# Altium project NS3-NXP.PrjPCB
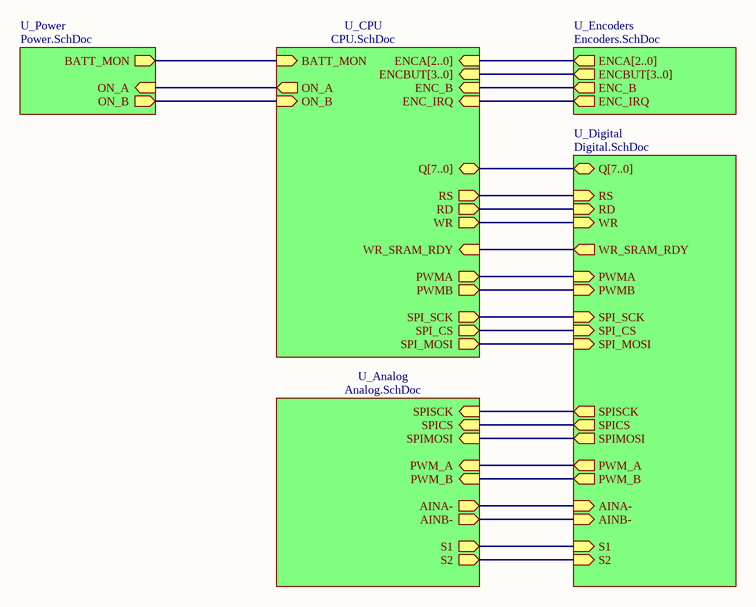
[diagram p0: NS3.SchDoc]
6 sheets, 304 parts. Net scope: hierarchical (ports join the sheet entries above them; power ports are global).
Board file: NS3-NXP.PcbDoc
Sheets:
  NS3.SchDoc
    U_Analog = Analog.SchDoc
    U_CPU = CPU.SchDoc
    U_Power = Power.SchDoc
    U_Digital = Digital.SchDoc
    U_Encoders = Encoders.SchDoc

## Sheet NS3.SchDoc: NeilScope-3 NXP
size A4; Engineer: Serj_K; Revision: 1.1; SheetNumber: 1; SheetTotal: 6; PageSetup: Record=PageOptions|CenterHorizontal=True|CenterVertical=True|PrintScale=1.00|XCorrection=1.00|YCorrection=1.00|PrintKind=0|BorderSize=5000000|LeftOffset=0|BottomOffset=0|Orientation=2|PaperLength=1000|PaperWidth=1000|Scale=100|PaperSource=7|PrintQuality=-4|MediaType=1|DitherType=10|PaperKind=A4|PrintScaleMode=1

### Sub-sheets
U_Analog = Analog.SchDoc: PWM_A (in), PWM_B (in), AINA- (out), AINB- (out), SPISCK (in), SPICS (in), SPIMOSI (in), S1 (out), S2 (out)
U_CPU = CPU.SchDoc: Q[7..0] (bidir), BATT_MON (in), RS (out), RD (out), ON_B (in), ON_A (out), WR (out), WR_SRAM_RDY (in), ENCA[2..0] (in), ENCBUT[3..0] (in), ENC_B (in), ENC_IRQ (in), PWMA (out), PWMB (out), SPI_SCK (out), SPI_CS (out), SPI_MOSI (out)
U_Digital = Digital.SchDoc: AINA- (in), AINB- (in), WR_SRAM_RDY (out), RS (in), RD (in), WR (in), Q[7..0] (bidir), PWM_A (out), PWM_B (out), PWMA (in), PWMB (in), SPISCK (out), SPICS (out), SPIMOSI (out), SPI_SCK (in), SPI_CS (in), SPI_MOSI (in), S1 (in), S2 (in)
U_Encoders = Encoders.SchDoc: ENC_B (out), ENC_IRQ (out), ENCA[2..0] (out), ENCBUT[3..0] (out)
U_Power = Power.SchDoc: BATT_MON (out), ON_B (out), ON_A (in)

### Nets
ENC_B: sheet U_CPU/ENC_B, sheet U_Encoders/ENC_B
ENC_IRQ: sheet U_CPU/ENC_IRQ, sheet U_Encoders/ENC_IRQ
ON_A: sheet U_CPU/ON_A, sheet U_Power/ON_A
ON_B: sheet U_CPU/ON_B, sheet U_Power/ON_B
PWMA: sheet U_CPU/PWMA, sheet U_Digital/PWMA
PWMB: sheet U_CPU/PWMB, sheet U_Digital/PWMB
RD: sheet U_CPU/RD, sheet U_Digital/RD
RS: sheet U_CPU/RS, sheet U_Digital/RS
S1: sheet U_Analog/S1, sheet U_Digital/S1
S2: sheet U_Analog/S2, sheet U_Digital/S2
SPI_CS: sheet U_CPU/SPI_CS, sheet U_Digital/SPI_CS
SPI_MOSI: sheet U_CPU/SPI_MOSI, sheet U_Digital/SPI_MOSI
SPI_SCK: sheet U_CPU/SPI_SCK, sheet U_Digital/SPI_SCK
SPICS: sheet U_Analog/SPICS, sheet U_Digital/SPICS
SPIMOSI: sheet U_Analog/SPIMOSI, sheet U_Digital/SPIMOSI
SPISCK: sheet U_Analog/SPISCK, sheet U_Digital/SPISCK
WR: sheet U_CPU/WR, sheet U_Digital/WR
WR_SRAM_RDY: sheet U_CPU/WR_SRAM_RDY, sheet U_Digital/WR_SRAM_RDY
NetC84_2: sheet U_CPU/BATT_MON, sheet U_Power/BATT_MON
NetR105_2: sheet U_Analog/PWM_A, sheet U_Digital/PWM_A
NetR125_2: sheet U_Analog/PWM_B, sheet U_Digital/PWM_B
NetU4_3: sheet U_Analog/AINA-, sheet U_Digital/AINA-
NetU4_10: sheet U_Analog/AINB-, sheet U_Digital/AINB-

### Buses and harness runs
bus sheet U_CPU/ENCA[2..0] = sheet U_Encoders/ENCA[2..0]
bus sheet U_CPU/ENCBUT[3..0] = sheet U_Encoders/ENCBUT[3..0]
bus sheet U_CPU/Q[7..0] = sheet U_Digital/Q[7..0]

## Sheet Analog.SchDoc: NeilScope-3 NXP   Analog
size A4; Engineer: Serj_K; Revision: 1.1; SheetNumber: 2; SheetTotal: 6
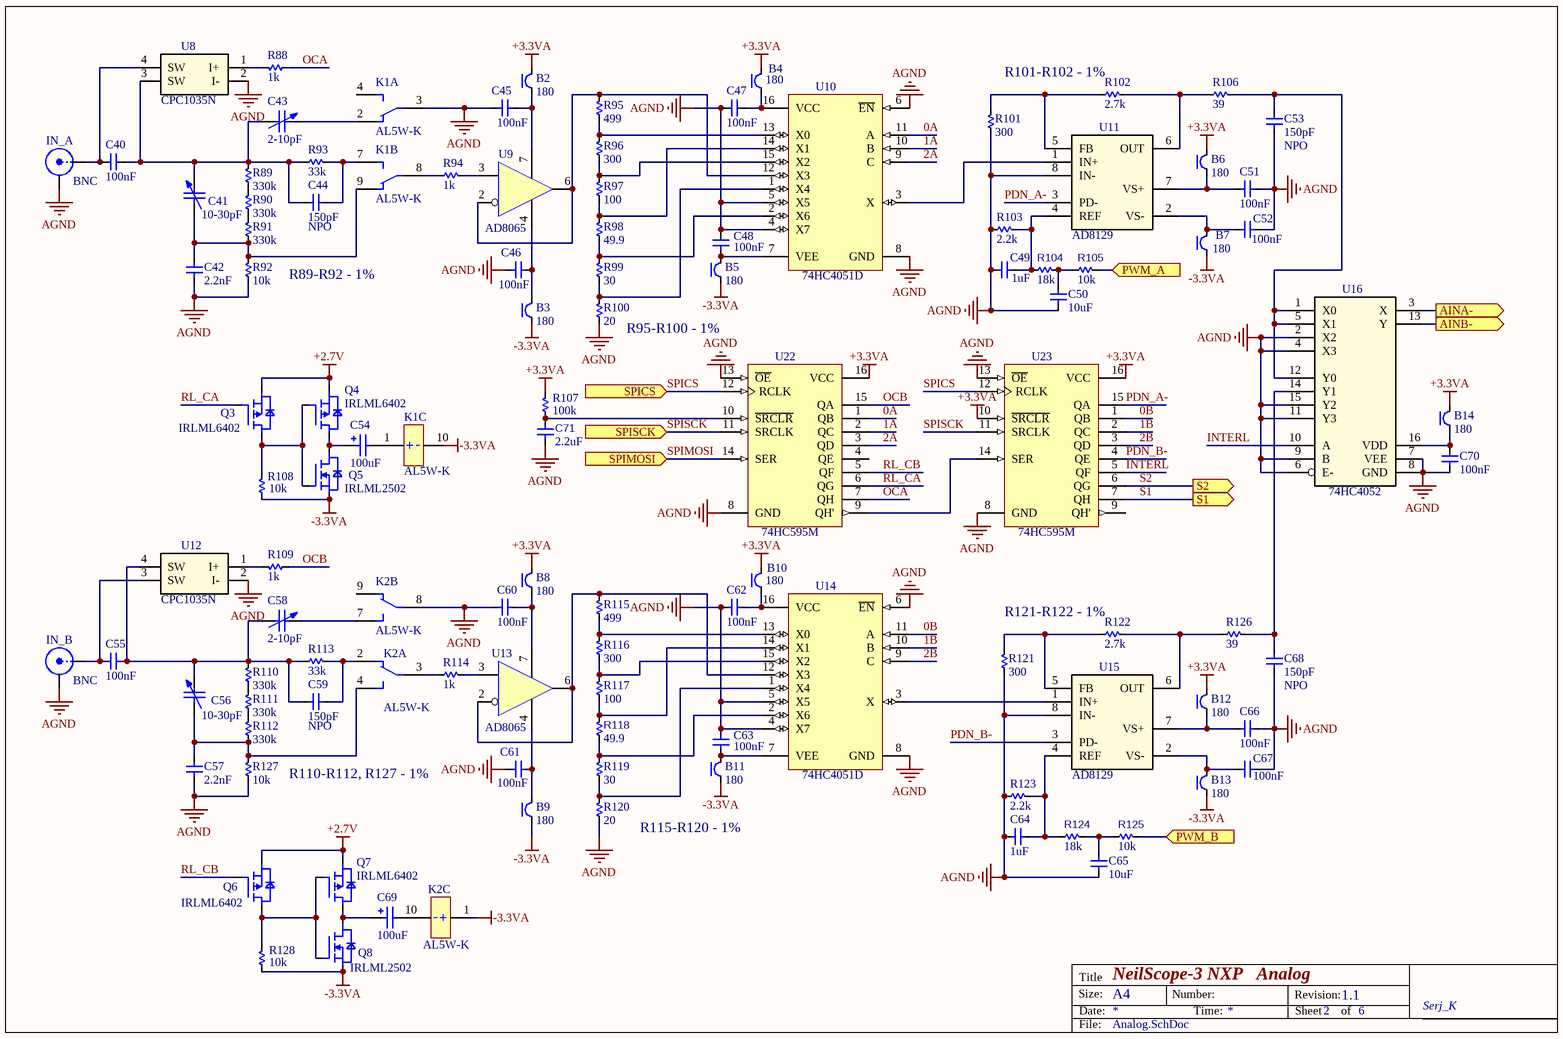
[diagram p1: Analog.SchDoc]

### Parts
B2  value 180  [C0603NH080]  (hidden comment: BEAD)
B3  value 180  [C0603NH080]  (hidden comment: BEAD)
B4  value 180  [C0603NH080]  (hidden comment: BEAD)
B5  value 180  [C0603NH080]  (hidden comment: BEAD)
B6  value 180  [C0603NH080]  (hidden comment: BEAD)
B7  value 180  [C0603NH080]  (hidden comment: BEAD)
B8  value 180  [C0603NH080]  (hidden comment: BEAD)
B9  value 180  [C0603NH080]  (hidden comment: BEAD)
B10  value 180  [C0603NH080]  (hidden comment: BEAD)
B11  value 180  [C0603NH080]  (hidden comment: BEAD)
B12  value 180  [C0603NH080]  (hidden comment: BEAD)
B13  value 180  [C0603NH080]  (hidden comment: BEAD)
B14  value 180  [C0603NH080]  (hidden comment: BEAD)
C40  value 100nF  [C1206NH190]  (hidden comment: Cap)
C41  value 10-30pF  [Cap_Var]  (hidden comment: Cap_Var)
C42  value 2.2nF  [C0805NH145]  (hidden comment: Cap)
C43  value 2-10pF  [Cap_Var]  (hidden comment: Cap_Var)
C44  NPO  value 150pF  [C0603NH080]
C45  value 100nF  [C0603NH080]  (hidden comment: Cap)
C46  value 100nF  [C0603NH080]  (hidden comment: Cap)
C47  value 100nF  [C0603NH080]  (hidden comment: Cap)
C48  value 100nF  [C0603NH080]  (hidden comment: Cap)
C49  value 1uF  [C0603NH080]  (hidden comment: Cap)
C50  value 10uF  [C0805NH145]  (hidden comment: Cap)
C51  value 100nF  [C0603NH080]  (hidden comment: Cap)
C52  value 100nF  [C0603NH080]  (hidden comment: Cap)
C53  NPO  value 150pF  [C0603NH080]
C54  CE_Al  [CE_D8_3.5]  (value not drawn)
C55  value 100nF  [C1206NH190]  (hidden comment: Cap)
C56  value 10-30pF  [Cap_Var]  (hidden comment: Cap_Var)
C57  value 2.2nF  [C0805NH145]  (hidden comment: Cap)
C58  value 2-10pF  [Cap_Var]  (hidden comment: Cap_Var)
C59  NPO  value 150pF  [C0603NH080]
C60  value 100nF  [C0603NH080]  (hidden comment: Cap)
C61  value 100nF  [C0603NH080]  (hidden comment: Cap)
C62  value 100nF  [C0603NH080]  (hidden comment: Cap)
C63  value 100nF  [C0603NH080]  (hidden comment: Cap)
C64  value 1uF  [C0603NH080]  (hidden comment: Cap)
C65  value 10uF  [C0805NH145]  (hidden comment: Cap)
C66  value 100nF  [C0603NH080]  (hidden comment: Cap)
C67  value 100nF  [C0603NH080]  (hidden comment: Cap)
C68  NPO  value 150pF  [C0603NH080]
C69  CE_Al  [CE_D8_3.5]  (value not drawn)
C70  value 100nF  [C0603NH080]  (hidden comment: Cap)
C71  value 2.2uF  [C0603_Murata]  (hidden comment: Cap)
IN_A  BNC  [BNC_RA CON]
IN_B  BNC  [BNC_RA CON]
K1  Part Label: AL5W-K  [DIP10_Relay]  (hidden comment: AxW-K-x)  (parts A,B,C of 3)
K2  Part Label: AL5W-K  [DIP10_Relay]  (hidden comment: AxW-K-x)  (parts A,B,C of 3)
Q3  Part Label: IRLML6402  [SOT23-3_DISCRETE]  (hidden comment: IRLML6302)
Q4  Part Label: IRLML6402  [SOT23-3_DISCRETE]  (hidden comment: IRLML6302)
Q5  Part Label: IRLML2502  [SOT23-3_DISCRETE]  (hidden comment: IRLML2402)
Q6  Part Label: IRLML6402  [SOT23-3_DISCRETE]  (hidden comment: IRLML6302)
Q7  Part Label: IRLML6402  [SOT23-3_DISCRETE]  (hidden comment: IRLML6302)
Q8  Part Label: IRLML2502  [SOT23-3_DISCRETE]  (hidden comment: IRLML2402)
R88  value 1k  [R0603N]  (hidden comment: R)
R89  value 330k  [R0805NH070]  (hidden comment: R)
R90  value 330k  [R0805NH070]  (hidden comment: R)
R91  value 330k  [R0805NH070]  (hidden comment: R)
R92  value 10k  [R0805NH070]  (hidden comment: R)
R93  value 33k  [R0805NH070]  (hidden comment: R)
R94  value 1k  [R0805NH070]  (hidden comment: R)
R95  value 499  [R0603N]  (hidden comment: R)
R96  value 300  [R0603N]  (hidden comment: R)
R97  value 100  [R0603N]  (hidden comment: R)
R98  value 49.9  [R0603N]  (hidden comment: R)
R99  value 30  [R0603N]  (hidden comment: R)
R100  value 20  [R0603N]  (hidden comment: R)
R101  value 300  [R0603N]  (hidden comment: R)
R102  value 2.7k  [R0603N]  (hidden comment: R)
R103  value 2.2k  [R0603N]  (hidden comment: R)
R104  value 18k  [R0805_YAGEO]  (hidden comment: R)
R105  value 10k  [R0603_UniOhm]  (hidden comment: R)
R106  value 39  [R0603N]  (hidden comment: R)
R107  value 100k  [R0603N]  (hidden comment: R)
R108  value 10k  [R0603N]  (hidden comment: R)
R109  value 1k  [R0603N]  (hidden comment: R)
R110  value 330k  [R0805NH070]  (hidden comment: R)
R111  value 330k  [R0805NH070]  (hidden comment: R)
R112  value 330k  [R0805NH070]  (hidden comment: R)
R113  value 33k  [R0805NH070]  (hidden comment: R)
R114  value 1k  [R0805NH070]  (hidden comment: R)
R115  value 499  [R0603N]  (hidden comment: R)
R116  value 300  [R0603N]  (hidden comment: R)
R117  value 100  [R0603N]  (hidden comment: R)
R118  value 49.9  [R0805_UniOhm]  (hidden comment: R)
R119  value 30  [R0603N]  (hidden comment: R)
R120  value 20  [R0603N]  (hidden comment: R)
R121  value 300  [R0603N]  (hidden comment: R)
R122  value 2.7k  [R0603N]  (hidden comment: R)
R123  value 2.2k  [R0603N]  (hidden comment: R)
R124  value 18k  [R0805_YAGEO]  (hidden comment: R)
R125  value 10k  [R0603_UniOhm]  (hidden comment: R)
R126  value 39  [R0603N]  (hidden comment: R)
R127  value 10k  [R0805NH070]  (hidden comment: R)
R128  value 10k  [R0603N]  (hidden comment: R)
U8  CPC1035N  [SOIC-4N]
U9  AD8065  [SO8_N]
U10  74HC4051D  [751B-05_N]
U11  AD8129  [SO8_N]
U12  CPC1035N  [SOIC-4N]
U13  AD8065  [SO8_N]
U14  74HC4051D  [751B-05_N]
U15  AD8129  [SO8_N]
U16  74HC4052  [TSSOP16A]
U22  74HC595M  [SO16_N]
U23  74HC595M  [SO16_N]

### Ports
AINA- (out), AINB- (out), PWM_A (in), PWM_B (in), S1 (out), S2 (out), SPICS (in), SPIMOSI (in), SPISCK (in)

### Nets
+2.7V: Q3.2(S) Q4.2(S) Q6.2(S) Q7.2(S)
+3.3VA: B2.2 B4.2 B6.2 B8.2 B10.2 B12.2 B14.2 R107.2 U22.16(VCC) U23.10(~{SRCLR}) U23.16(VCC)
-3.3VA: B3.1 B5.1 B7.1 B9.1 B11.1 B13.1 K1.10(-) K2.1(+) Q5.2(S) Q8.2(S) R108.1 R128.1
AGND: C42.1 C45.1 C46.1 C47.2 C48.2 C49.1 C50.1 C51.2 C52.2 C53.1 C57.1 C60.1 C61.1 C62.2 C63.2 C64.1 C65.1 C66.2 C67.2 C68.1 C70.1 C71.1 IN_A.2(Y) IN_B.2(Y) K1.3(K1) K2.8(K2) R92.1 R100.1 R101.1 R103.1 R120.1 R121.1 R123.1 R127.1 U8.2(I-) U10.4(X7) U10.5(X5) U10.6(~{EN}) U10.8(GND) U11.8(IN-) U12.2(I-) U14.4(X7) U14.5(X5) U14.6(~{EN}) U14.8(GND) U15.8(IN-) U16.2(X2) U16.4(X3) U16.6(E-) U16.7(VEE) U16.8(GND) U16.9(B) U16.11(Y3) U16.15(Y2) U22.8(GND) U22.13(~{OE}) U23.8(GND) U23.13(~{OE})
0A: U10.11(A) U22.1(QB)
0B: U14.11(A) U23.1(QB)
1A: U10.10(B) U22.2(QC)
1B: U14.10(B) U23.2(QC)
2A: U10.9(C) U22.3(QD)
2B: U14.9(C) U23.3(QD)
INTERL: U16.10(A) U23.5(QF)
OCA: R88.1 U22.7(QH)
OCB: R109.1 U22.15(QA)
PDN_A-: U11.3(PD-) U23.15(QA)
PDN_B-: U15.3(PD-) U23.4(QE)
RL_CA: Q3.1(G) U22.6(QG)
RL_CB: Q6.1(G) U22.5(QF)
S1: U23.7(QH) ; port S1
S2: U23.6(QG) ; port S2
SPICS: U22.12(RCLK) U23.12(RCLK) ; port SPICS
SPIMOSI: U22.14(SER) ; port SPIMOSI
SPISCK: U22.11(SRCLK) U23.11(SRCLK) ; port SPISCK
NetB2_1: B2.1 C45.2 U9.7
NetB3_2: B3.2 C46.2 U9.4
NetB4_1: B4.1 C47.1 U10.16(VCC)
NetB5_2: B5.2 C48.1 U10.7(VEE)
NetB6_1: B6.1 C51.1 U11.7(VS+)
NetB7_2: B7.2 C52.1 U11.2(VS-)
NetB8_1: B8.1 C60.2 U13.7
NetB9_2: B9.2 C61.2 U13.4
NetB10_1: B10.1 C62.1 U14.16(VCC)
NetB11_2: B11.2 C63.1 U14.7(VEE)
NetB12_1: B12.1 C66.1 U15.7(VS+)
NetB13_2: B13.2 C67.1 U15.2(VS-)
NetB14_1: B14.1 C70.2 U16.16(VDD)
NetC40_1: C40.1 IN_A.1(X) U8.4(SW)
NetC40_2: C40.2 C41.2 C43.1 C44.1 R89.2 R93.1 U8.3(SW)
NetC41_1: C41.1 C42.2 K1.9(K21) R91.1 R92.2
NetC43_2: C43.2 K1.2(K11)
NetC44_2: C44.2 K1.7(K22) R93.2
NetC49_2: C49.2 R103.2 R104.1 U11.4(REF)
NetC50_2: C50.2 R104.2 R105.1
NetC53_2: C53.2 R106.2 U16.1(X0) U16.5(X1) U16.12(Y0)
NetC54_1: C54.1 Q4.3(D) Q5.3(D)
NetC54_2: C54.2 K1.1(+)
NetC55_1: C55.1 IN_B.1(X) U12.3(SW)
NetC55_2: C55.2 C56.2 C58.1 C59.1 R110.2 R113.1 U12.4(SW)
NetC56_1: C56.1 C57.2 K2.4(K12) R112.1 R127.2
NetC58_2: C58.2 K2.7(K22)
NetC59_2: C59.2 K2.2(K11) R113.2
NetC64_2: C64.2 R123.2 R124.1 U15.4(REF)
NetC65_2: C65.2 R124.2 R125.1
NetC68_2: C68.2 R126.2 U16.14(Y1)
NetC69_1: C69.1 Q7.3(D) Q8.3(D)
NetC69_2: C69.2 K2.10(-)
NetC71_2: C71.2 R107.1 U22.10(~{SRCLR})
NetK1_8: K1.8(K2) R94.1
NetK2_3: K2.3(K1) R114.1
NetQ3_3: Q3.3(D) Q4.1(G) Q5.1(G) R108.2
NetQ6_3: Q6.3(D) Q7.1(G) Q8.1(G) R128.2
NetR88_2: R88.2 U8.1(I+)
NetR89_1: R89.1 R90.2
NetR90_1: R90.1 R91.2
NetR94_2: R94.2 U9.3(In)
NetR95_1: R95.1 R96.2 U10.13(X0)
NetR95_2: R95.2 U9.2(In-) U9.6(Out) U10.12(X3)
NetR96_1: R96.1 R97.2 U10.15(X2)
NetR97_1: R97.1 R98.2 U10.14(X1)
NetR98_1: R98.1 R99.2 U10.2(X6)
NetR99_1: R99.1 R100.2 U10.1(X4)
NetR101_2: R101.2 R102.1 U11.5(FB)
NetR102_2: R102.2 R106.1 U11.6(OUT)
NetR105_2: R105.2 ; port PWM_A
NetR109_2: R109.2 U12.1(I+)
NetR110_1: R110.1 R111.2
NetR111_1: R111.1 R112.2
NetR114_2: R114.2 U13.3(In)
NetR115_1: R115.1 R116.2 U14.13(X0)
NetR115_2: R115.2 U13.2(In-) U13.6(Out) U14.12(X3)
NetR116_1: R116.1 R117.2 U14.15(X2)
NetR117_1: R117.1 R118.2 U14.14(X1)
NetR118_1: R118.1 R119.2 U14.2(X6)
NetR119_1: R119.1 R120.2 U14.1(X4)
NetR121_2: R121.2 R122.1 U15.5(FB)
NetR122_2: R122.2 R126.1 U15.6(OUT)
NetR125_2: R125.2 ; port PWM_B
NetU4_3: U16.3(X) ; port AINA-
NetU4_10: U16.13(Y) ; port AINB-
NetU10_3: U10.3(X) U11.1(IN+)
NetU14_3: U14.3(X) U15.1(IN+)
NetU22_9: U22.9(QH') U23.14(SER)

Not connected (* = marked no-connect by the designer): K1 4(K12); K2 9(K21); U22 4(QE); U23 9(QH')

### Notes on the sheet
- (near R102) R101-R102 - 1%
- R89-R92 - 1%
- R95-R100 - 1%
- (near R122) R121-R122 - 1%
- R110-R112, R127 - 1%
- R115-R120 - 1%

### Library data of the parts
B2-B14 = BLM18PG181SN1D: Bead 0603 size for power lines; Part Label: SMD Beads 180 1.5A; Manufacturer: muRata; Device: EMI; ShortName: SMD Beads
C40 C55 = GRM31C5C1H104JA01L: PartName: GRM31; Part Label: C1206 100nF 5% NP0 50V; Manufacturer: muRata; Voltage: 50V; Tolerance: 5 %; Device: C; ShortName: C1206
C41 C43 C56 C58 = Cap_Var: Variable or Adjustable Capacitor
C42 C57 = CL21C222JBFNNNE: PartName: CL21; Part Label: C0805 2.2nF 5% NP0 50V; Manufacturer: Samsung Electro-Mechanics; Voltage: 50V; Tolerance: 5 %; Device: C; ShortName: C0805
C44 C53 C59 C68 = C0603C151J5GAC7867: PartName: C0603C; Part Label: C0603 150pF 5% NP0 50V; Manufacturer: Kemet; Voltage: 50V; Tolerance: 5 %; Device: C; ShortName: C0603
C45-C48 C51 C52 C60-C63 C66 C67 C70 = CL10B104KB8NNNC: PartName: CL10; Part Label: C0603 100nF 10% X7R 50V; Manufacturer: Samsung Electro-Mechanics; Voltage: 50V; Tolerance: 10 %; Device: C; ShortName: C0603
C49 C64 = GRM188R61C225KE15D: PartName: GRM188; Part Label: C0603 2.2uF 10% X5R 16V; Manufacturer: muRata; Voltage: 16V; Tolerance: 10 %; Device: C; ShortName: C0603
C50 C65 = GRM21BR61A106KE19L: PartName: GRM21; Part Label: C0805 10uF 10% X5R 10V; Manufacturer: muRata; Voltage: 10V; Tolerance: 10 %; Device: C; ShortName: C0805
C54 C69 = CE_Al: Aluminium Electrolitic Capacitor
C71 = GRM188R61C225KE15D: General Purpose; PartName: GRM188; Part Label: C0603 2.2uF 10% X5R 16V; Manufacturer: muRata; Voltage: 16V; Tolerance: 10 %; Device: C; ShortName: C0603
IN_A IN_B = BNC: BNC Elbow Connector
K1 K2 = A–5W–K: 5V переключающее реле.; Part Number: A–5W–K; Manufacturer: Fujitsu; ClassName_u: Relay; Device: K
Q3 Q4 Q6 Q7 = IRLML6302TRPBF: 20V, 0.7A Single P-Channel HEXFET Power MOSFET; Manufacturer: International Rectifier; Device: Q; ShortName: PMOS
Q5 Q8 = IRLML2402TRPBF: 20V, 0.25 Ohm, Single N-Channel HEXFET Power MOSFET; Manufacturer: International Rectifier; Device: Q; ShortName: NMOS
R88 R109 = ERA3AED102V: PartName: ERA3A; Part Label: R0603 1k 0.5% TC25 75V; Manufacturer: Panasonic; TempCo: 25 ppm; Tolerance: 0.5 %; ClassName_u: SMD 0603 Thin Film; ShortName: R0603
R89-R91 R110-R112 R127 = 0805S8F5100T50: PartName: 0805S; Part Label: R0805 510 1% TC100 150V; Manufacturer: uniOhm; TempCo: 100 ppm; Tolerance: 1 %; ShortName: R0805
R92 R93 R113 = 0805S8F1002T50: PartName: 0805S; Part Label: R0805 10k 1% TC100 150V; Manufacturer: uniOhm; TempCo: 100 ppm; Tolerance: 1 %; ShortName: R0805
R94 R114 = 0805S8F1001T50: PartName: 0805S; Part Label: R0805 1k 1% TC100 150V; Manufacturer: uniOhm; TempCo: 100 ppm; Tolerance: 1 %; ShortName: R0805
R95 R115 = TC0350F4990T5E: TC03 (0603) 1/16W 1% 499E 50PPM T/R-5000; Part Label: R0603 499 1% TC50 50V; Manufacturer: uniOhm; ClassName_u: SMD 0603 Thin Film; ShortName: R0603
R96 R101 R116 R121 = 0603SAF3300T50: PartName: 0603SA; Part Label: R0603 330 1% TC100 50V; Manufacturer: uniOhm; TempCo: 100 ppm; Tolerance: 1 %; ShortName: R0603
R97 R117 = 0603SAF1000T50: PartName: 0603SA; Part Label: R0603 100 1% TC100 50V; Manufacturer: uniOhm; TempCo: 100 ppm; Tolerance: 1 %; ShortName: R0603
R98 = RR0816P-4992-D-68C: PartName: RR0816; Part Label: R0603 49.9k 0.5% TC25 50V; Manufacturer: SUSUMU; TempCo: 25 ppm; Tolerance: 0.5 %; ClassName_u: SMD 0603 Thin Film; ShortName: R0603
R99 R100 R119 R120 = 0603SAF330JT50: PartName: 0603SA; Part Label: R0603 33 1% TC100 50V; Manufacturer: uniOhm; TempCo: 100 ppm; Tolerance: 1 %; ShortName: R0603
R102 R103 R122 R123 = 0603SAF2701T50: PartName: 0603SA; Part Label: R0603 2.7k 1% TC100 50V; Manufacturer: uniOhm; TempCo: 100 ppm; Tolerance: 1 %; ShortName: R0603
R104 R124 = RC0805FR-0710KL: General Purpose Chip Resistor; Part Label: R0805 10k 1% TC100 300V; Manufacturer: YAGEO; TempCo: 100 ppm; Tolerance: 1 %; ShortName: R0805
R105 R125 = TC0350F1002T5E: TC03 (0603) 1/16W 1% 10.0K 50PPM T/R-5000; Part Label: R0603 10k 1% TC50 50V; Manufacturer: uniOhm; ClassName_u: SMD 0603 Thin Film; ShortName: R0603
R106 R126 = TC0310C3001T5E: TC03 (0603) 1/16W 0.25% 3.00K 10PPM T/R-5000; Part Label: R0603 3k 0.25% TC10 50V; Manufacturer: uniOhm; ClassName_u: SMD 0603 Thin Film; ShortName: R0603
R107 R108 R128 = 0603SAF1002T50: PartName: 0603SA; Part Label: R0603 10k 1% TC100 50V; Manufacturer: uniOhm; TempCo: 100 ppm; Tolerance: 1 %; ShortName: R0603
R118 = 0805S8F4700T50: PartName: 0805S; Part Label: R0805 470 1% TC100 150V; Manufacturer: uniOhm; TempCo: 100 ppm; Tolerance: 1 %; ShortName: R0805
U8 U12 = CPC1035N: Opto Switch
U10 U14 = MC74HC4051AD: Analog Multiplexer/Demultiplexer
U22 U23 = M74HC595M1R: 8 Bit Shift Register with Output Latches (3 STATE)

## Sheet CPU.SchDoc: NeilScope-3 NXP    CPU
size A4; Engineer: Serj_K; Revision: 1.1; SheetNumber: 3; SheetTotal: 6; PageSetup: Record=PageOptions|CenterHorizontal=True|CenterVertical=True|PrintScale=0.97|XCorrection=1.00|YCorrection=1.00|PrintKind=0|BorderSize=5000000|LeftOffset=0|BottomOffset=0|Orientation=2|PaperLength=1000|PaperWidth=1000|Scale=100|PaperSource=7|PrintQuality=-4|MediaType=1|DitherType=10|PaperKind=A4|PrintScaleMode=1
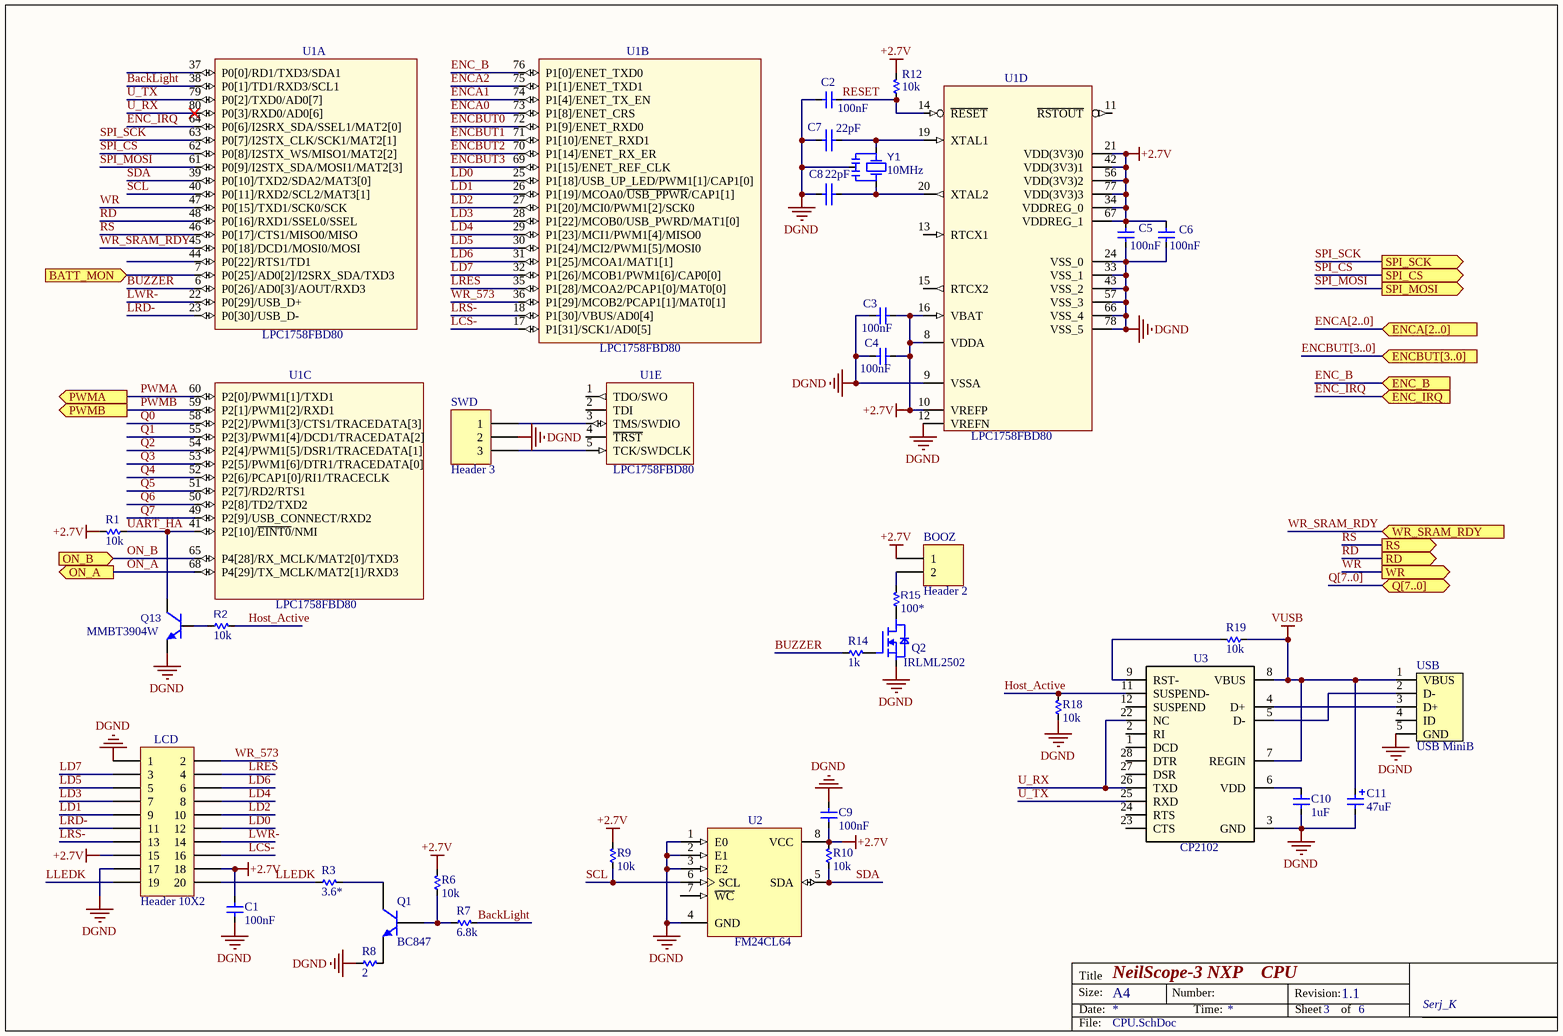
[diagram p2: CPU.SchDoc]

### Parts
BOOZ  Header 2  [HDR1X2]
C1  value 100nF  [C0603NH080]  (hidden comment: Cap)
C2  value 100nF  [C0603NH080]  (hidden comment: Cap)
C3  value 100nF  [C0603NH080]  (hidden comment: Cap)
C4  value 100nF  [C0603NH080]  (hidden comment: Cap)
C5  value 100nF  [C0603NH080]  (hidden comment: Cap)
C6  value 100nF  [C0603NH080]  (hidden comment: Cap)
C7  value 22pF  [C0603_Samsung]  (hidden comment: Cap)
C8  value 22pF  [C0603_Samsung]  (hidden comment: Cap)
C9  value 100nF  [C0603NH080]  (hidden comment: Cap)
C10  value 1uF  [C0603NH080]  (hidden comment: Cap)
C11  value 47uF  [CAPMP7343X280N]  (hidden comment: ECap)
LCD  Header 10X2  [HDR2X10]
Q1  BC847  [SOT23_N]
Q2  Part Label: IRLML2502  [SOT23-3_DISCRETE]  (hidden comment: IRLML2402)
Q13  Part Label: MMBT3904W  [SOT323]  (hidden comment: NPN)
R1  value 10k  [R0603_UniOhm]  (hidden comment: R)
R2  value 10k  [R0603_UniOhm]  (hidden comment: R)
R3  value 3.6*  [R1206NH084]  (hidden comment: R)
R6  value 10k  [R0603N]  (hidden comment: R)
R7  value 6.8k  [R0603N]  (hidden comment: R)
R8  value 2  [R1206NH084]  (hidden comment: R)
R9  value 10k  [R0603N]  (hidden comment: R)
R10  value 10k  [R0603N]  (hidden comment: R)
R12  value 10k  [R0603N]  (hidden comment: R)
R14  value 1k  [R0603N]  (hidden comment: R)
R15  value 100*  [R0603_UniOhm]  (hidden comment: R)
R18  value 10k  [R0603N]  (hidden comment: R)
R19  value 10k  [R0603N]  (hidden comment: R)
SWD  Header 3  [HDR1X3]
U1  LPC1758FBD80  [PQFP80]  (parts A,B,C,D,E of 5)
U2  FM24CL64  [SOP8_N]
U3  CP2102  [QFN-28]
USB  USB MiniB  [USB miniB (SMD NNM)]
Y1  value 10MHz  [CSTCE_G]  (hidden comment: XTAL_CAP)

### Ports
BATT_MON (in), ENC_B (in), ENC_IRQ (in), ENCA[2..0] (in), ENCBUT[3..0] (in), ON_A (out), ON_B (in), PWMA (out), PWMB (out), Q[7..0] (bidir), RD (out), RS (out), SPI_CS (out), SPI_MOSI (out), SPI_SCK (out), WR (out), WR_SRAM_RDY (in)

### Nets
+2.7V: BOOZ.1 C1.2 C3.2 C4.2 C5.2 C6.2 C9.1 LCD.15 LCD.18 R1.2 R6.2 R9.2 R10.2 R12.2 U1.8(VDDA) U1.10(VREFP) U1.16(VBAT) U1.21(VDD(3V3)0) U1.34(VDDREG_0) U1.42(VDD(3V3)1) U1.56(VDD(3V3)2) U1.67(VDDREG_1) U1.77(VDD(3V3)3) U2.8(VCC)
DGND: C1.1 C2.2 C3.1 C4.1 C5.1 C6.1 C7.1 C8.1 C9.2 C10.1 C11.C LCD.1 LCD.17 Q2.2(S) Q13.2(E) R8.1 R18.1 SWD.2 U1.9(VSSA) U1.12(VREFN) U1.24(VSS_0) U1.33(VSS_1) U1.43(VSS_2) U1.57(VSS_3) U1.66(VSS_4) U1.78(VSS_5) U2.1(E0) U2.2(E1) U2.3(E2) U2.4(GND) U3.3(GND) USB.5(GND) Y1.2(G)
VUSB: C11.A R19.1 U3.7(REGIN) U3.8(VBUS) USB.1(VBUS)
BackLight: R7.2 U1.38(P0[1]/TD1/RXD3/SCL1)
BUZZER: R14.1 U1.6(P0[26]/AD0[3]/AOUT/RXD3)
ENC_B: U1.76(P1[0]/ENET_TXD0) ; port ENC_B
ENC_IRQ: U1.64(P0[6]/I2SRX_SDA/SSEL1/MAT2[0]) ; port ENC_IRQ
ENCA0: U1.73(P1[8]/ENET_CRS)
ENCA1: U1.74(P1[4]/ENET_TX_EN)
ENCA2: U1.75(P1[1]/ENET_TXD1)
ENCBUT0: U1.72(P1[9]/ENET_RXD0)
ENCBUT1: U1.71(P1[10]/ENET_RXD1)
ENCBUT2: U1.70(P1[14]/ENET_RX_ER)
ENCBUT3: U1.69(P1[15]/ENET_REF_CLK)
Host_Active: R2.2 R18.2 U3.11(SUSPEND-)
LCS-: LCD.16 U1.17(P1[31]/SCK1/AD0[5])
LD0: LCD.12 U1.25(P1[18]/USB_UP_LED/PWM1[1]/CAP1[0])
LD1: LCD.9 U1.26(P1[19]/MCOA0/~{USB_PPWR}/CAP1[1])
LD2: LCD.10 U1.27(P1[20]/MCI0/PWM1[2]/SCK0)
LD3: LCD.7 U1.28(P1[22]/MCOB0/USB_PWRD/MAT1[0])
LD4: LCD.8 U1.29(P1[23]/MCI1/PWM1[4]/MISO0)
LD5: LCD.5 U1.30(P1[24]/MCI2/PWM1[5]/MOSI0)
LD6: LCD.6 U1.31(P1[25]/MCOA1/MAT1[1])
LD7: LCD.3 U1.32(P1[26]/MCOB1/PWM1[6]/CAP0[0])
LLEDK: LCD.19 LCD.20 R3.1
LRD-: LCD.11 U1.23(P0[30]/USB_D-)
LRES: LCD.4 U1.35(P1[28]/MCOA2/PCAP1[0]/MAT0[0])
LRS-: LCD.13 U1.18(P1[30]/VBUS/AD0[4])
LWR-: LCD.14 U1.22(P0[29]/USB_D+)
ON_A: U1.68(P4[29]/TX_MCLK/MAT2[1]/RXD3) ; port ON_A
ON_B: U1.65(P4[28]/RX_MCLK/MAT2[0]/TXD3) ; port ON_B
PWMA: U1.60(P2[0]/PWM1[1]/TXD1) ; port PWMA
PWMB: U1.59(P2[1]/PWM1[2]/RXD1) ; port PWMB
Q0: U1.58(P2[2]/PWM1[3]/CTS1/TRACEDATA[3])
Q1: U1.55(P2[3]/PWM1[4]/DCD1/TRACEDATA[2])
Q2: U1.54(P2[4]/PWM1[5]/DSR1/TRACEDATA[1])
Q3: U1.53(P2[5]/PWM1[6]/DTR1/TRACEDATA[0])
Q4: U1.52(P2[6]/PCAP1[0]/RI1/TRACECLK)
Q5: U1.51(P2[7]/RD2/RTS1)
Q6: U1.50(P2[8]/TD2/TXD2)
Q7: U1.49(P2[9]/USB_CONNECT/RXD2)
RD: U1.48(P0[16]/RXD1/SSEL0/SSEL) ; port RD
RESET: C2.1 R12.1 U1.14(~{RESET})
RS: U1.46(P0[17]/CTS1/MISO0/MISO) ; port RS
SCL: R9.1 U1.40(P0[11]/RXD2/SCL2/MAT3[1]) U2.6(SCL)
SDA: R10.1 U1.39(P0[10]/TXD2/SDA2/MAT3[0]) U2.5(SDA)
SPI_CS: U1.62(P0[8]/I2STX_WS/MISO1/MAT2[2]) ; port SPI_CS
SPI_MOSI: U1.61(P0[9]/I2STX_SDA/MOSI1/MAT2[3]) ; port SPI_MOSI
SPI_SCK: U1.63(P0[7]/I2STX_CLK/SCK1/MAT2[1]) ; port SPI_SCK
U_RX: U1.80(P0[3]/RXD0/AD0[6]) U3.22(NC) U3.26(TXD)
U_TX: U1.79(P0[2]/TXD0/AD0[7]) U3.25(RXD)
UART_HA: Q13.3(C) R1.1 U1.41(P2[10]/~{EINT0}/NMI)
WR: U1.47(P0[15]/TXD1/SCK0/SCK) ; port WR
WR_573: LCD.2 U1.36(P1[29]/MCOB2/PCAP1[1]/MAT0[1])
WR_SRAM_RDY: U1.45(P0[18]/DCD1/MOSI0/MOSI) ; port WR_SRAM_RDY
NetBOOZ_2: BOOZ.2 R15.2
NetC7_2: C7.2 U1.19(XTAL1) Y1.1(OSC1)
NetC8_2: C8.2 U1.20(XTAL2) Y1.3(OSC2)
NetC10_2: C10.2 U3.6(VDD)
NetC84_2: U1.7(P0[25]/AD0[2]/I2SRX_SDA/TXD3) ; port BATT_MON
NetQ1_1: Q1.1(B) R6.1 R7.1
NetQ1_2: Q1.2(E) R8.2
NetQ1_3: Q1.3(C) R3.2
NetQ2_1: Q2.1(G) R14.2
NetQ2_3: Q2.3(D) R15.1
NetQ13_1: Q13.1(B) R2.1
NetR19_2: R19.2 U3.9(RST-)
NetSWD_1: SWD.1 U1.3(TMS/SWDIO)
NetSWD_3: SWD.3 U1.5(TCK/SWDCLK)
NetU3_4: U3.4(D+) USB.3(D+)
NetU3_5: U3.5(D-) USB.2(D-)

Not connected (* = marked no-connect by the designer): U1 1(TDO/SWO) 2(TDI) 4(~{TRST}) 11(~{RSTOUT}) 13(RTCX1) 15(RTCX2) 37(P0[0]/RD1/TXD3/SDA1) 44(P0[22]/RTS1/TD1); U2 7(~{WC}); U3 1(DCD) 2(RI) 12(SUSPEND) 23(CTS) 24(RTS) 27(DSR) 28(DTR); USB 4(ID)

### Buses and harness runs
bus ENCA[2..0] = port ENCA[2..0]
bus ENCBUT[3..0] = port ENCBUT[3..0]
bus Q[7..0] = port Q[7..0]

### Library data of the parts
BOOZ = Header 2: Header, 2-Pin
C1-C6 C9 = CL10B104KB8NNNC: as C45 on sheet Analog
C7 C8 = CL10C220JB8NNNC: PartName: CL10; Part Label: C0603 22pF 5% NP0 50V; Manufacturer: Samsung Electro-Mechanics; Voltage: 50V; Tolerance: 5 %; Device: C; ShortName: C0603
C10 = GRM188R61C225KE15D: as C49 on sheet Analog
C11 = 293D476X9010D2T: PartName: 293D; Part Label: SMD Tantal 47uF 10% 10V; Manufacturer: Vishay; Voltage: 10V; Tolerance: 10 %; ClassName_u: SMD Tantal; Device: C
LCD = Header 10X2: Header, 10-Pin, Dual row
Q1 = BC847: NPN General-purpose Transistor
Q2 = IRLML2402TRPBF: as Q5 on sheet Analog
Q13 = MMBT3904WT1G: 40 V, 200 mA NPN general-purpose transistors; PartName: 3904W; Manufacturer: ON Semiconductor; Device: Q
R1 R2 R9 R10 R12 R18 R19 = 0603SAF1002T50: as R107 on sheet Analog
R3 R8 = CRCW12062R00FKEA: Part Label: R1206 2 1% TC100 200V; Manufacturer: Vishay; TempCo: 100 ppm; Tolerance: 1 %; ShortName: R1206
R6 = TC0350F1002T5E: as R105 on sheet Analog
R7 = TC0350F5101T5E: TC03 (0603) 1/16W 1% 5.1K 50PPM T/R-5000; Part Label: R0603 5.1k 1% TC50 50V; Manufacturer: uniOhm; ClassName_u: SMD 0603 Thin Film; ShortName: R0603
R14 = ERJ3EKF1001V: PartName: ERJ3E; Part Label: R0603 1k 1% TC100 50V; Manufacturer: Panasonic; TempCo: 100 ppm; Tolerance: 1 %; ShortName: R0603
R15 = 0603SAF1000T50: as R97 on sheet Analog
SWD = Header 3: Header, 3-Pin
U1 = LPC1758FBD80,551: 32-bit ARM Cortex-M3 MCU, 512kB flash 32kB SRAM with Ethernet, USB 2.0 Host/Device/OTG, CAN; Manufacturer: NXP Semiconductors; Device: U
U2 = M24C64MN1: 64 Kbit Serial I²C Bus EEPROM
U3 = CP2102: USB-RS232 Converter
USB = USB MINIB: Manufacturer: Unknown; Device: J
Y1 = CSTCE10M0G55Z-R0: SMD 10 MHz 0.5%, 0.2%(TC) Build in Load Capacitance 33pF ± 20%; Manufacturer: muRata; ClassName_u: Ceramic Resonators SMD; Device: Y

## Sheet Power.SchDoc: NeilScope-3 NXP     Power
size A4; Engineer: Serj_K; Revision: 1.1; SheetNumber: 5; SheetTotal: 6; PageSetup: Record=PageOptions|CenterHorizontal=True|CenterVertical=True|PrintScale=0.97|XCorrection=1.00|YCorrection=1.00|PrintKind=2|BorderSize=5000000|LeftOffset=0|BottomOffset=0|Orientation=2|PaperLength=1000|PaperWidth=1000|Scale=100|PaperSource=7|PrintQuality=-4|MediaType=1|DitherType=10|PaperKind=A4|PrintScaleMode=1
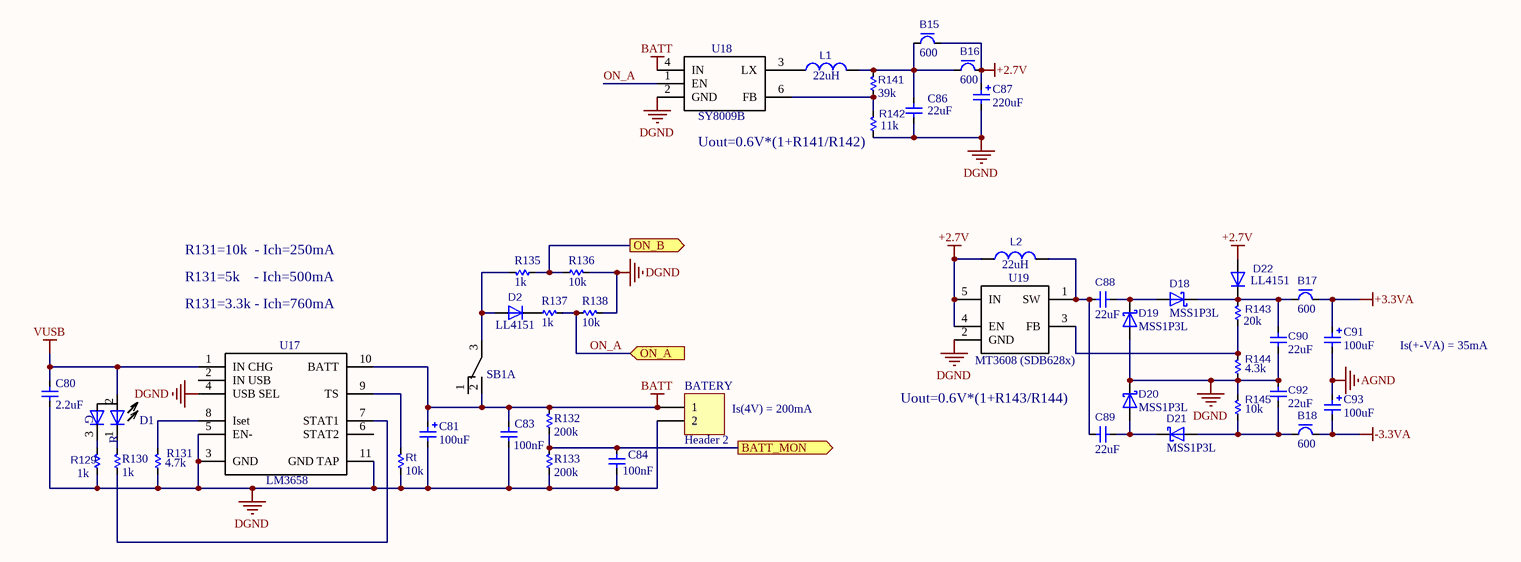
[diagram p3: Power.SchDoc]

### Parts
B15  value 600  [BEAD0603]  (hidden comment: BEAD)
B16  value 600  [BEAD0603]  (hidden comment: BEAD)
B17  value 600  [BEAD0603]  (hidden comment: BEAD)
B18  value 600  [BEAD0603]  (hidden comment: BEAD)
BATERY  Header 2  [HDR1X2]
C80  value 2.2uF  [C0805NH145]  (hidden comment: Cap)
C81  value 100uF  [CAPMP7343X280N]  (hidden comment: ECap)
C83  value 100nF  [C0603NH080]  (hidden comment: Cap)
C84  value 100nF  [C0603NH080]  (hidden comment: Cap)
C86  value 22uF  [C1206NH190]  (hidden comment: Cap)
C87  value 220uF  [CAPMP7343X280N]  (hidden comment: ECap)
C88  value 22uF  [C1206_Murata]  (hidden comment: Cap)
C89  value 22uF  [C1206_Murata]  (hidden comment: Cap)
C90  value 22uF  [C1206_Murata]  (hidden comment: Cap)
C91  value 100uF  [CAPMP7343X280N]  (hidden comment: ECap)
C92  value 22uF  [C1206_Murata]  (hidden comment: Cap)
C93  value 100uF  [CAPMP7343X280N]  (hidden comment: ECap)
D1  LightDiode  [D_C_LightDiode_3pin_D3]  (value not drawn)
D2  Part Label: LL4151  [SOD80_VISHAY_MINIMELF]  (hidden comment: Diode)
D18  Part Label: MSS1P3L  [SOD323FL_VISHAY_MICROSMP]  (hidden comment: D_Schottky)
D19  Part Label: MSS1P3L  [SOD323FL_VISHAY_MICROSMP]  (hidden comment: D_Schottky)
D20  Part Label: MSS1P3L  [SOD323FL_VISHAY_MICROSMP]  (hidden comment: D_Schottky)
D21  Part Label: MSS1P3L  [SOD323FL_VISHAY_MICROSMP]  (hidden comment: D_Schottky)
D22  Part Label: LL4151  [SOD80_VISHAY_MINIMELF]  (hidden comment: Diode)
L1  value 22uH  [L2424_TAIYO_NR60XX]  (hidden comment: L)
L2  value 22uH  [L2424_TAIYO_NR60XX]  (hidden comment: L)
R129  value 1k  [R0603_Pan_ERJ3]  (hidden comment: R)
R130  value 1k  [R0603N]  (hidden comment: R)
R131  value 4.7k  [R0603N]  (hidden comment: R)
R132  value 200k  [R0603N]  (hidden comment: R)
R133  value 200k  [R0603N]  (hidden comment: R)
R135  value 1k  [R0603N]  (hidden comment: R)
R136  value 10k  [R0603N]  (hidden comment: R)
R137  value 1k  [R0603N]  (hidden comment: R)
R138  value 10k  [R0603N]  (hidden comment: R)
R141  value 39k  [R0805_UniOhm]  (hidden comment: R)
R142  value 11k  [R0805_UniOhm]  (hidden comment: R)
R143  value 20k  [R0603_UniOhm]  (hidden comment: R)
R144  value 4.3k  [R0603_UniOhm]  (hidden comment: R)
R145  value 10k  [R0603_UniOhm]  (hidden comment: R)
Rt  value 10k  [R0603_UniOhm]  (hidden comment: R)
SB1  SB_8x8  [SB_8x8]  (value not drawn)  (part A of 2)
U17  LM3658  [WSON10]
U18  SY8009B  [SOT-23-6]
U19  MT3608 (SDB628x)  [1262-01]

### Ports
BATT_MON (out), ON_A (in), ON_B (out)

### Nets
+2.7V: B15.2 B16.2 C87.A D22.A L2.1 U19.4(EN) U19.5(IN)
+3.3VA: B17.2 C91.A
-3.3VA: B18.2 C93.C
AGND: C91.C C93.A
BATT: BATERY.1 C81.A C83.2 R132.2 SB1.2 U17.10(BATT) U18.4(IN)
DGND: BATERY.2 C80.1 C81.C C83.1 C84.1 C86.1 C87.C C90.1 C92.2 D19.A D20.C R129.1 R131.1 R133.1 R136.2 R138.2 R142.1 R144.1 R145.2 Rt.1 U17.3(GND) U17.4(USB_SEL) U17.5(EN-) U17.11(GND_TAP) U18.2(GND) U19.2(GND)
VUSB: C80.2 D1.2 U17.1(IN_CHG)
ON_A: R137.2 R138.1 U18.1(EN) ; port ON_A
ON_B: R135.1 R136.1 ; port ON_B
NetB15_1: B15.1 B16.1 C86.2 L1.2 R141.2
NetB17_1: B17.1 C90.2 D18.C D22.C R143.2
NetB18_1: B18.1 C92.1 D21.A R145.1
NetC84_2: C84.2 R132.1 R133.2 ; port BATT_MON
NetC88_1: C88.1 C89.1 L2.2 U19.1(SW)
NetC88_2: C88.2 D18.A D19.C
NetC89_2: C89.2 D20.A D21.C
NetD1_1: D1.1 R130.2
NetD1_3: D1.3 R129.2
NetD2_A: D2.A R135.2 SB1.3
NetD2_C: D2.C R137.1
NetL1_1: L1.1 U18.3(LX)
NetR130_1: R130.1 U17.7(STAT1)
NetR131_2: R131.2 U17.8(Iset)
NetR141_1: R141.1 R142.2 U18.6(FB)
NetR143_1: R143.1 R144.2 U19.3(FB)
NetRt_2: Rt.2 U17.9(TS)

Not connected (* = marked no-connect by the designer): SB1 1; U17 2(IN_USB) 6(STAT2)

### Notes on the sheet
- (near R142) Uout=0.6V*(1+R141/R142)
- R131=10k  - Ich=250mA
- R131=5k    - Ich=500mA
- R131=3.3k - Ich=760mA
- Is(+-VA) = 35mA
- (near BATERY) Is(4V) = 200mA
- Uout=0.6V*(1+R143/R144)

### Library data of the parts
B15-B18 = BLM18AG601SN1D: 0603 size for general signal lines; Part Label: SMD Beads 600 0.6A; Manufacturer: muRata; Device: EMI; ShortName: SMD Beads
BATERY = Header 2: Header, 2-Pin
C80 = GRM21BR61A106KE19L: as C50 on sheet Analog
C81 = 293D476X9010D2T: as C11 on sheet CPU
C83 C84 = CL10B104KB8NNNC: as C45 on sheet Analog
C86 C88-C90 C92 = GRM31CR71H475KA12L: PartName: GRM31; Part Label: C1206 4.7uF 10% X7R 50V; Manufacturer: muRata; Voltage: 50V; Tolerance: 10 %; Device: C; ShortName: C1206
C87 C91 C93 = TR3D107K016C0150: PartName: TR3D; Part Label: SMD Tantal 100uF 16V 1A; Manufacturer: Vishay; Voltage: 16V; ClassName_u: SMD Tantal; Device: C
D1 = D_C_LightDiode_3pin_OA
D2 D22 = LL4151-GS8: Small Signal Fast Switching Diode; Manufacturer: Vishay; ClassName_u: Switching SMD; Device: D
D18-D21 = MSS1P3L-M3/89A: 30V, 1A, eSMP, Surface Mount Schottky Barrier Rectifiers; PartName: MSSXPXX; Manufacturer: Vishay; ClassName_u: Schottky SMD; Device: D
L1 L2 = NR6028T220M: Shielded Power Inductor Wire Wound H=2.8mm; PartName: NR60XX; Part Label: L2525 22uH 20% 1.3A; Manufacturer: Taiyo Yuden; Tolerance: 20 %; ShortName: L2525
R129 = ERJ3EKF1001V: as R14 on sheet CPU
R130 R135 = ERA3AED102V: as R88 on sheet Analog
R131 = 0603SAF2001T50: PartName: 0603SA; Part Label: R0603 2k 1% TC100 50V; Manufacturer: uniOhm; TempCo: 100 ppm; Tolerance: 1 %; ShortName: R0603
R132 = 0603SAF1503T50: PartName: 0603SA; Part Label: R0603 150k 1% TC100 50V; Manufacturer: uniOhm; TempCo: 100 ppm; Tolerance: 1 %; ShortName: R0603
R133 R138 = 0603SAF1003T50: PartName: 0603SA; Part Label: R0603 100k 1% TC100 50V; Manufacturer: uniOhm; TempCo: 100 ppm; Tolerance: 1 %; ShortName: R0603
R136 R137 Rt = 0603SAF1002T50: as R107 on sheet Analog
R141 R142 = 0805S8F1502T50: PartName: 0805S; Part Label: R0805 15k 1% TC100 150V; Manufacturer: uniOhm; TempCo: 100 ppm; Tolerance: 1 %; ShortName: R0805
R143-R145 = 0603SAF2201T50: PartName: 0603SA; Part Label: R0603 2.2k 1% TC100 50V; Manufacturer: uniOhm; TempCo: 100 ppm; Tolerance: 1 %; ShortName: R0603
U17 = LM3658: Li-Ion Battery Charger
U18 = SY8009B: DC-DC Step-Down converter
U19 = MT3608: 2A Step Up Converter

## Sheet Digital.SchDoc: NeilScope-3 NXP   Digital
size A4; Author: Serj_K; DrawnBy: Serj_K; Engineer: Serj_K; Revision: 1.1; SheetNumber: 4; SheetTotal: 6; PageSetup: Record=PageOptions|CenterHorizontal=True|CenterVertical=True|PrintScale=0.97|XCorrection=1.00|YCorrection=1.00|PrintKind=2|BorderSize=5000000|LeftOffset=0|BottomOffset=0|Orientation=2|PaperLength=1000|PaperWidth=1000|Scale=100|PaperSource=7|PrintQuality=-4|MediaType=1|DitherType=10|PaperKind=A4|PrintScaleMode=1
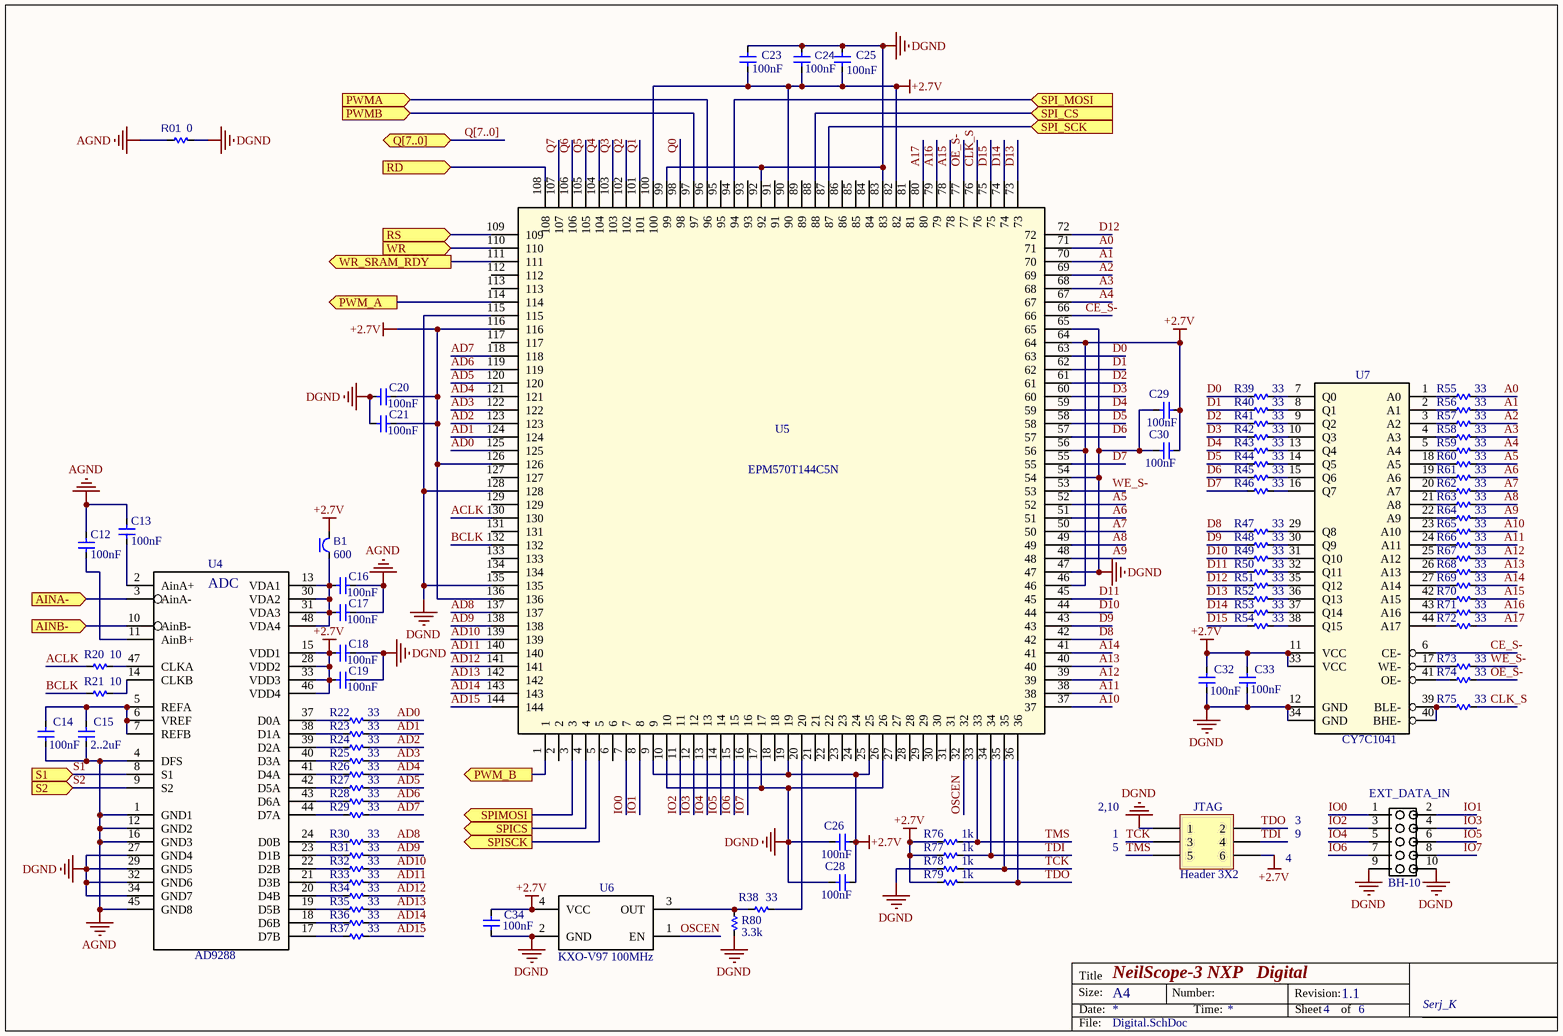
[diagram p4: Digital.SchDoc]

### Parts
B1  value 600  [BEAD0603]  (hidden comment: BEAD)
C12  value 100nF  [C0603NH080]  (hidden comment: Cap)
C13  value 100nF  [C0603NH080]  (hidden comment: Cap)
C14  value 100nF  [C0603NH080]  (hidden comment: Cap)
C15  value 2..2uF  [C0805NH145]  (hidden comment: Cap)
C16  value 100nF  [C0603NH080]  (hidden comment: Cap)
C17  value 100nF  [C0603NH080]  (hidden comment: Cap)
C18  value 100nF  [C0603NH080]  (hidden comment: Cap)
C19  value 100nF  [C0603NH080]  (hidden comment: Cap)
C20  value 100nF  [C0603NH080]  (hidden comment: Cap)
C21  value 100nF  [C0603NH080]  (hidden comment: Cap)
C23  value 100nF  [C0603NH080]  (hidden comment: Cap)
C24  value 100nF  [C0603_Samsung]  (hidden comment: Cap)
C25  value 100nF  [C0603NH080]  (hidden comment: Cap)
C26  value 100nF  [C0603NH080]  (hidden comment: Cap)
C28  value 100nF  [C0603NH080]  (hidden comment: Cap)
C29  value 100nF  [C0603NH080]  (hidden comment: Cap)
C30  value 100nF  [C0603NH080]  (hidden comment: Cap)
C32  value 100nF  [C0603NH080]  (hidden comment: Cap)
C33  value 100nF  [C0603NH080]  (hidden comment: Cap)
C34  value 100nF  [C0603NH080]  (hidden comment: Cap)
EXT_DATA_IN  BH-10  [BH-10]
JTAG  Header 3X2  [HDR2X3]
R01  value 0  [R0805_Susumu]  (hidden comment: R)  (graphical)
R20  value 10  [R0603N]  (hidden comment: R)
R21  value 10  [R0603N]  (hidden comment: R)
R22  value 33  [R0603N]  (hidden comment: R)
R23  value 33  [R0603N]  (hidden comment: R)
R24  value 33  [R0603N]  (hidden comment: R)
R25  value 33  [R0603N]  (hidden comment: R)
R26  value 33  [R0603N]  (hidden comment: R)
R27  value 33  [R0603N]  (hidden comment: R)
R28  value 33  [R0603N]  (hidden comment: R)
R29  value 33  [R0603N]  (hidden comment: R)
R30  value 33  [R0603N]  (hidden comment: R)
R31  value 33  [R0603N]  (hidden comment: R)
R32  value 33  [R0603N]  (hidden comment: R)
R33  value 33  [R0603N]  (hidden comment: R)
R34  value 33  [R0603N]  (hidden comment: R)
R35  value 33  [R0603N]  (hidden comment: R)
R36  value 33  [R0603N]  (hidden comment: R)
R37  value 33  [R0603N]  (hidden comment: R)
R38  value 33  [R0603N]  (hidden comment: R)
R39  value 33  [R0603N]  (hidden comment: R)
R40  value 33  [R0603N]  (hidden comment: R)
R41  value 33  [R0603N]  (hidden comment: R)
R42  value 33  [R0603N]  (hidden comment: R)
R43  value 33  [R0603N]  (hidden comment: R)
R44  value 33  [R0603N]  (hidden comment: R)
R45  value 33  [R0603N]  (hidden comment: R)
R46  value 33  [R0603N]  (hidden comment: R)
R47  value 33  [R0603N]  (hidden comment: R)
R48  value 33  [R0603N]  (hidden comment: R)
R49  value 33  [R0603N]  (hidden comment: R)
R50  value 33  [R0603N]  (hidden comment: R)
R51  value 33  [R0603N]  (hidden comment: R)
R52  value 33  [R0603N]  (hidden comment: R)
R53  value 33  [R0603N]  (hidden comment: R)
R54  value 33  [R0603N]  (hidden comment: R)
R55  value 33  [R0603N]  (hidden comment: R)
R56  value 33  [R0603N]  (hidden comment: R)
R57  value 33  [R0603N]  (hidden comment: R)
R58  value 33  [R0603N]  (hidden comment: R)
R59  value 33  [R0603N]  (hidden comment: R)
R60  value 33  [R0603N]  (hidden comment: R)
R61  value 33  [R0603N]  (hidden comment: R)
R62  value 33  [R0603N]  (hidden comment: R)
R63  value 33  [R0603N]  (hidden comment: R)
R64  value 33  [R0603N]  (hidden comment: R)
R65  value 33  [R0603N]  (hidden comment: R)
R66  value 33  [R0603N]  (hidden comment: R)
R67  value 33  [R0603N]  (hidden comment: R)
R68  value 33  [R0603N]  (hidden comment: R)
R69  value 33  [R0603N]  (hidden comment: R)
R70  value 33  [R0603N]  (hidden comment: R)
R71  value 33  [R0603N]  (hidden comment: R)
R72  value 33  [R0603N]  (hidden comment: R)
R73  value 33  [R0603N]  (hidden comment: R)
R74  value 33  [R0603N]  (hidden comment: R)
R75  value 33  [R0603N]  (hidden comment: R)
R76  value 1k  [R0603N]  (hidden comment: R)
R77  value 1k  [R0603N]  (hidden comment: R)
R78  value 1k  [R0603N]  (hidden comment: R)
R79  value 1k  [R0603N]  (hidden comment: R)
R80  value 3.3k  [R0603N]  (hidden comment: R)
U4  AD9288  [TQFP48_N]
U5  EPM570T144C5N  [TQFP144_N]
U6  KXO-V97 100MHz  [KXO-V97]
U7  CY7C1041  [TSOP-44-II]

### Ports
AINA- (in), AINB- (in), PWM_A (out), PWM_B (out), PWMA (in), PWMB (in), Q[7..0] (bidir), RD (in), RS (in), S1 (in), S2 (in), SPI_CS (in), SPI_MOSI (in), SPI_SCK (in), SPICS (out), SPIMOSI (out), SPISCK (out), WR (in), WR_SRAM_RDY (out)

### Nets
+2.7V: B1.2 C18.1 C19.1 C20.2 C21.2 C23.1 C24.1 C25.1 C26.1 C28.1 C29.1 C30.1 C32.1 C33.1 C34.1 JTAG.6 R76.1 R77.1 R79.1 U4.15(VDD1) U4.28(VDD2) U4.33(VDD3) U4.46(VDD4) U5.9 U5.19 U5.25 U5.46 U5.56 U5.64 U5.82 U5.90 U5.100 U5.116 U5.126 U5.136 U6.4(VCC) U7.11(VCC) U7.33(VCC)
AGND: C12.2 C13.2 C14.2 C15.1 C16.2 C17.2 R01.1 U4.1(GND1) U4.4(DFS) U4.12(GND2) U4.16(GND3) U4.45(GND8)
DGND: C18.2 C19.2 C20.1 C21.1 C23.2 C24.2 C25.2 C26.2 C28.2 C29.2 C30.2 C32.2 C33.2 C34.2 EXT_DATA_IN.9 EXT_DATA_IN.10 JTAG.1 R01.2 R78.1 R80.2 U4.27(GND4) U4.29(GND5) U4.32(GND6) U4.34(GND7) U5.10 U5.17 U5.26 U5.47 U5.54 U5.65 U5.83 U5.92 U5.99 U5.115 U5.128 U5.135 U6.2(GND) U7.12(GND) U7.34(GND)
A0: R55.2 U5.71
A1: R56.2 U5.70
A2: R57.2 U5.69
A3: R58.2 U5.68
A4: R59.2 U5.67
A5: R60.2 U5.52
A6: R61.2 U5.51
A7: R62.2 U5.50
A8: R63.2 U5.49
A9: R64.2 U5.48
A10: R65.2 U5.37
A11: R66.2 U5.38
A12: R67.2 U5.39
A13: R68.2 U5.40
A14: R69.2 U5.41
A15: R70.2 U5.78
A16: R71.2 U5.79
A17: R72.2 U5.80
ACLK: R20.1 U5.130
AD0: R22.2 U5.125
AD1: R23.2 U5.124
AD2: R24.2 U5.123
AD3: R25.2 U5.122
AD4: R26.2 U5.121
AD5: R27.2 U5.120
AD6: R28.2 U5.119
AD7: R29.2 U5.118
AD8: R30.2 U5.137
AD9: R31.2 U5.138
AD10: R32.2 U5.139
AD11: R33.2 U5.140
AD12: R34.2 U5.141
AD13: R35.2 U5.142
AD14: R36.2 U5.143
AD15: R37.2 U5.144
BCLK: R21.1 U5.132
CE_S-: U5.66 U7.6(CE-)
CLK_S: R75.2 U5.76
D0: R39.1 U5.63
D1: R40.1 U5.62
D2: R41.1 U5.61
D3: R42.1 U5.60
D4: R43.1 U5.59
D5: R44.1 U5.58
D6: R45.1 U5.57
D7: R46.1 U5.55
D8: R47.1 U5.42
D9: R48.1 U5.43
D10: R49.1 U5.44
D11: R50.1 U5.45
D12: R51.1 U5.72
D13: R52.1 U5.73
D14: R53.1 U5.74
D15: R54.1 U5.75
IO0: EXT_DATA_IN.1 U5.7
IO1: EXT_DATA_IN.2 U5.8
IO2: EXT_DATA_IN.3 U5.11
IO3: EXT_DATA_IN.4 U5.12
IO4: EXT_DATA_IN.5 U5.13
IO5: EXT_DATA_IN.6 U5.14
IO6: EXT_DATA_IN.7 U5.15
IO7: EXT_DATA_IN.8 U5.16
OE_S-: R74.2 U5.77
OSCEN: U5.32 U6.1(EN)
PWMA: U5.96 ; port PWMA
PWMB: U5.97 ; port PWMB
Q0: U5.98
Q1: U5.101
Q2: U5.102
Q3: U5.103
Q4: U5.104
Q5: U5.105
Q6: U5.106
Q7: U5.107
RD: U5.108 ; port RD
RS: U5.109 ; port RS
S1: U4.8(S1) ; port S1
S2: U4.9(S2) ; port S2
SPI_CS: U5.88 ; port SPI_CS
SPI_MOSI: U5.94 ; port SPI_MOSI
SPI_SCK: U5.87 ; port SPI_SCK
SPICS: U5.4 ; port SPICS
SPIMOSI: U5.3 ; port SPIMOSI
SPISCK: U5.5 ; port SPISCK
TCK: JTAG.3 R78.2 U5.35
TDI: JTAG.4 R77.2 U5.34
TDO: JTAG.2 R79.2 U5.36
TMS: JTAG.5 R76.2 U5.33
WE_S-: R73.2 U5.53
WR: U5.110 ; port WR
WR_SRAM_RDY: U5.111 ; port WR_SRAM_RDY
NetB1_1: B1.1 C16.1 C17.1 U4.13(VDA1) U4.30(VDA2) U4.31(VDA3) U4.48(VDA4)
NetC12_1: C12.1 U4.11(AinB+)
NetC13_1: C13.1 U4.2(AinA+)
NetC14_1: C14.1 C15.2 U4.5(REFA) U4.6(VREF) U4.7(REFB)
NetR20_2: R20.2 U4.47(CLKA)
NetR21_2: R21.2 U4.14(CLKB)
NetR22_1: R22.1 U4.37(D0A)
NetR23_1: R23.1 U4.38(D1A)
NetR24_1: R24.1 U4.39(D2A)
NetR25_1: R25.1 U4.40(D3A)
NetR26_1: R26.1 U4.41(D4A)
NetR27_1: R27.1 U4.42(D5A)
NetR28_1: R28.1 U4.43(D6A)
NetR29_1: R29.1 U4.44(D7A)
NetR30_1: R30.1 U4.24(D0B)
NetR31_1: R31.1 U4.23(D1B)
NetR32_1: R32.1 U4.22(D2B)
NetR33_1: R33.1 U4.21(D3B)
NetR34_1: R34.1 U4.20(D4B)
NetR35_1: R35.1 U4.19(D5B)
NetR36_1: R36.1 U4.18(D6B)
NetR37_1: R37.1 U4.17(D7B)
NetR38_1: R38.1 R80.1 U6.3(OUT)
NetR38_2: R38.2 U5.20
NetR39_2: R39.2 U7.7(Q0)
NetR40_2: R40.2 U7.8(Q1)
NetR41_2: R41.2 U7.9(Q2)
NetR42_2: R42.2 U7.10(Q3)
NetR43_2: R43.2 U7.13(Q4)
NetR44_2: R44.2 U7.14(Q5)
NetR45_2: R45.2 U7.15(Q6)
NetR46_2: R46.2 U7.16(Q7)
NetR47_2: R47.2 U7.29(Q8)
NetR48_2: R48.2 U7.30(Q9)
NetR49_2: R49.2 U7.31(Q10)
NetR50_2: R50.2 U7.32(Q11)
NetR51_2: R51.2 U7.35(Q12)
NetR52_2: R52.2 U7.36(Q13)
NetR53_2: R53.2 U7.37(Q14)
NetR54_2: R54.2 U7.38(Q15)
NetR55_1: R55.1 U7.1(A0)
NetR56_1: R56.1 U7.2(A1)
NetR57_1: R57.1 U7.3(A2)
NetR58_1: R58.1 U7.4(A3)
NetR59_1: R59.1 U7.5(A4)
NetR60_1: R60.1 U7.18(A5)
NetR61_1: R61.1 U7.19(A6)
NetR62_1: R62.1 U7.20(A7)
NetR63_1: R63.1 U7.21(A8)
NetR64_1: R64.1 U7.22(A9)
NetR65_1: R65.1 U7.23(A10)
NetR66_1: R66.1 U7.24(A11)
NetR67_1: R67.1 U7.25(A12)
NetR68_1: R68.1 U7.26(A13)
NetR69_1: R69.1 U7.27(A14)
NetR70_1: R70.1 U7.42(A15)
NetR71_1: R71.1 U7.43(A16)
NetR72_1: R72.1 U7.44(A17)
NetR73_1: R73.1 U7.17(WE-)
NetR74_1: R74.1 U7.41(OE-)
NetR75_1: R75.1 U7.39(BLE-) U7.40(BHE-)
NetR105_2: U5.114 ; port PWM_A
NetR125_2: U5.1 ; port PWM_B
NetU4_3: U4.3(AinA-) ; port AINA-
NetU4_10: U4.10(AinB-) ; port AINB-

Not connected (* = marked no-connect by the designer): U5 2 6 18 21 22 23 24 27 28 29 30 31 81 84 85 86 89 91 93 95 112 113 117 127 129 131 133 134

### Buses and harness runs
bus Q[7..0] = port Q[7..0]

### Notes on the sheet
- 2,10
- 1
- 5
- 3
- 9
- (near JTAG) 4

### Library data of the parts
B1 = BLM18PG181SN1D: as B2 on sheet Analog
C12-C14 C16-C21 C23-C26 C28-C30 C32-C34 = CL10B104KB8NNNC: as C45 on sheet Analog
C15 = GRM21BR61A106KE19L: as C50 on sheet Analog
EXT_DATA_IN = BH-10_2
JTAG = Header 3X2: Header, 3-Pin, Dual row
R01 = RR1220Q-100-D: PartName: RR1220; Part Label: R0805 10 0.5% TC50 100V; Manufacturer: SUSUMU; TempCo: 50 ppm; Tolerance: 0.5 %; ClassName_u: SMD 0805 Thin Film; ShortName: R0805
R20-R80 = 0603SAF330JT50: as R99 on sheet Analog
U4 = AD9288: 2 x 8bit 100MSPS ADC converter
U5 = QFP-144: PQFP-144/TQFP-144
U6 = KXO-V97: Clock Oscillator
U7 = CY7C1041: SRAM

## Sheet Encoders.SchDoc: NeilScope-3 NXP   Encoders
size A4; Engineer: Serj_K; Revision: 1.1; SheetNumber: 6; SheetTotal: 6
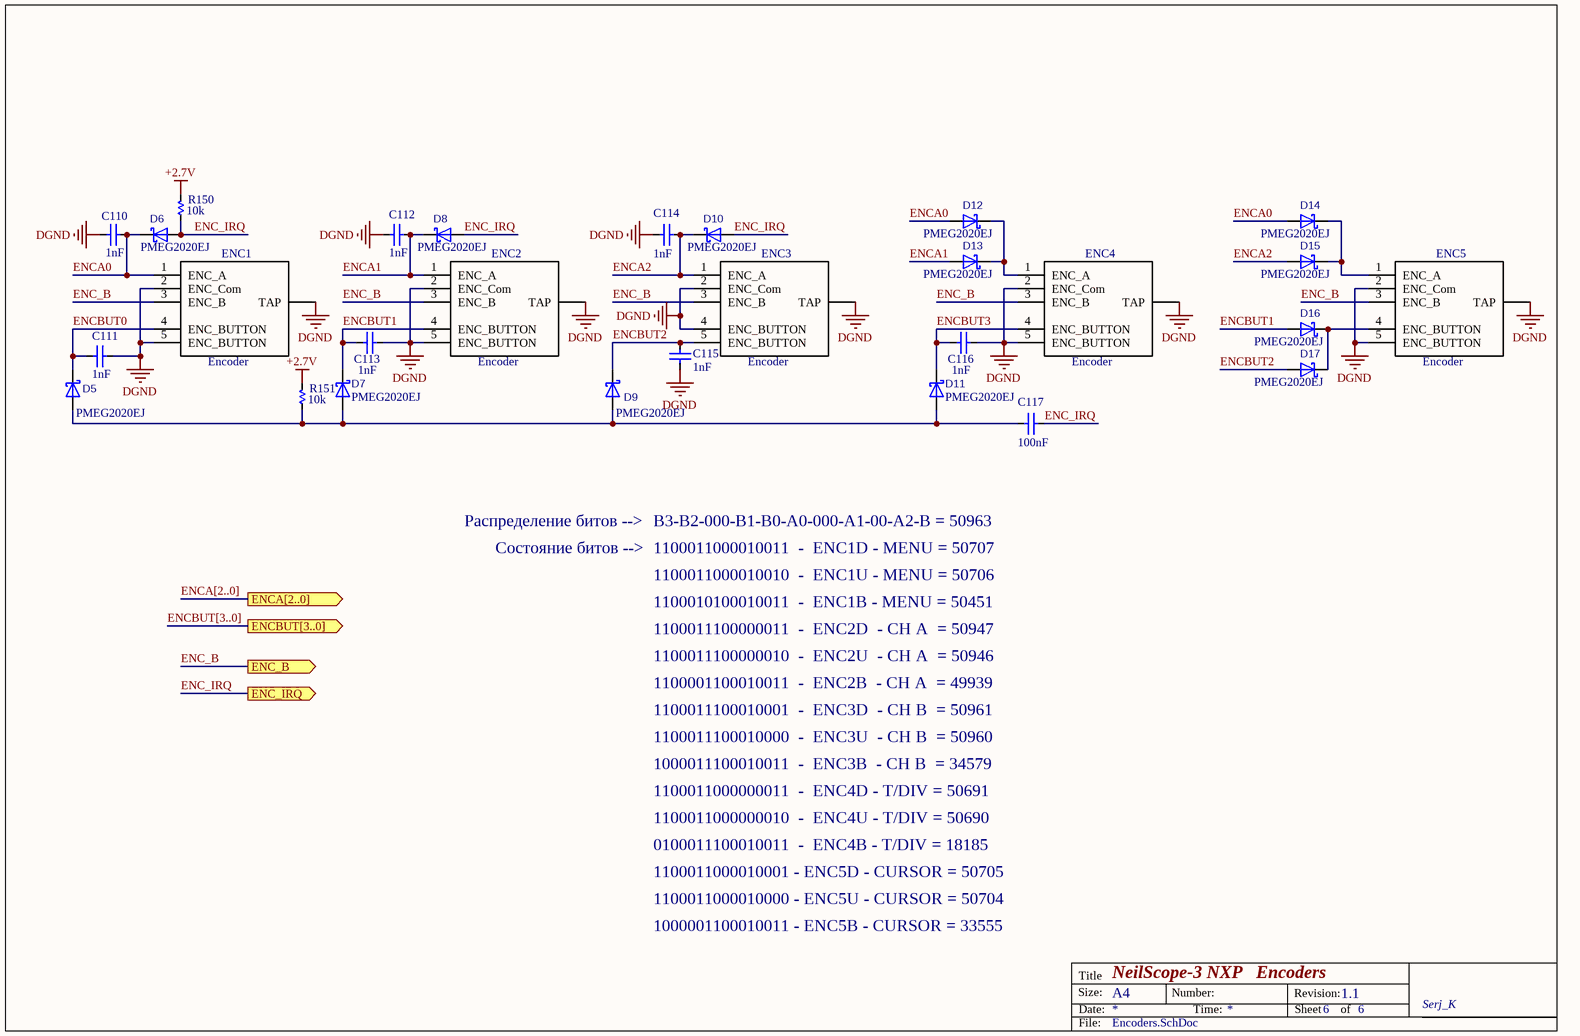
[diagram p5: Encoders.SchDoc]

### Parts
C110  value 1nF  [C0603_Samsung]  (hidden comment: Cap)
C111  value 1nF  [C0603_Samsung]  (hidden comment: Cap)
C112  value 1nF  [C0603_Samsung]  (hidden comment: Cap)
C113  value 1nF  [C0603_Samsung]  (hidden comment: Cap)
C114  value 1nF  [C0603_Samsung]  (hidden comment: Cap)
C115  value 1nF  [C0603_Samsung]  (hidden comment: Cap)
C116  value 1nF  [C0603_Samsung]  (hidden comment: Cap)
C117  value 100nF  [C0603_Samsung]  (hidden comment: Cap)
D5  Part Label: PMEG2020EJ  [SOD323FL_NXP]  (hidden comment: D_Schottky)
D6  Part Label: PMEG2020EJ  [SOD323FL_NXP]  (hidden comment: D_Schottky)
D7  Part Label: PMEG2020EJ  [SOD323FL_NXP]  (hidden comment: D_Schottky)
D8  Part Label: PMEG2020EJ  [SOD323FL_NXP]  (hidden comment: D_Schottky)
D9  Part Label: PMEG2020EJ  [SOD323FL_NXP]  (hidden comment: D_Schottky)
D10  Part Label: PMEG2020EJ  [SOD323FL_NXP]  (hidden comment: D_Schottky)
D11  Part Label: PMEG2020EJ  [SOD323FL_NXP]  (hidden comment: D_Schottky)
D12  Part Label: PMEG2020EJ  [SOD323FL_NXP]  (hidden comment: D_Schottky)
D13  Part Label: PMEG2020EJ  [SOD323FL_NXP]  (hidden comment: D_Schottky)
D14  Part Label: PMEG2020EJ  [SOD323FL_NXP]  (hidden comment: D_Schottky)
D15  Part Label: PMEG2020EJ  [SOD323FL_NXP]  (hidden comment: D_Schottky)
D16  Part Label: PMEG2020EJ  [SOD323FL_NXP]  (hidden comment: D_Schottky)
D17  Part Label: PMEG2020EJ  [SOD323FL_NXP]  (hidden comment: D_Schottky)
ENC1  Encoder  [Encoder]
ENC2  Encoder  [Encoder]
ENC3  Encoder  [Encoder]
ENC4  Encoder  [Encoder]
ENC5  Encoder  [Encoder]
R150  value 10k  [R0603_UniOhm]  (hidden comment: R)
R151  value 10k  [R0603_UniOhm]  (hidden comment: R)

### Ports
ENC_B (out), ENC_IRQ (out), ENCA[2..0] (out), ENCBUT[3..0] (out)

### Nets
+2.7V: R150.2 R151.2
DGND: C110.1 C111.1 C112.1 C113.2 C114.1 C115.2 C116.2 ENC1.0(TAP) ENC1.2(ENC_Com) ENC1.5(ENC_BUTTON) ENC2.0(TAP) ENC2.2(ENC_Com) ENC2.5(ENC_BUTTON) ENC3.0(TAP) ENC3.2(ENC_Com) ENC3.4(ENC_BUTTON) ENC4.0(TAP) ENC4.2(ENC_Com) ENC4.5(ENC_BUTTON) ENC5.0(TAP) ENC5.2(ENC_Com) ENC5.5(ENC_BUTTON)
ENC_B: ENC1.3(ENC_B) ENC2.3(ENC_B) ENC3.3(ENC_B) ENC4.3(ENC_B) ENC5.3(ENC_B) ; port ENC_B
ENC_IRQ: C117.2 D6.A D8.A D10.A R150.1 ; port ENC_IRQ
ENCA0: C110.2 D6.C D12.A D14.A ENC1.1(ENC_A)
ENCA1: C112.2 D8.C D13.A ENC2.1(ENC_A)
ENCA2: C114.2 D10.C D15.A ENC3.1(ENC_A)
ENCBUT0: C111.2 D5.C ENC1.4(ENC_BUTTON)
ENCBUT1: C113.1 D7.C D16.A ENC2.4(ENC_BUTTON)
ENCBUT2: C115.1 D9.C D17.A ENC3.5(ENC_BUTTON)
ENCBUT3: C116.1 D11.C ENC4.4(ENC_BUTTON)
NetC117_1: C117.1 D5.A D7.A D9.A D11.A R151.1
NetD12_C: D12.C D13.C ENC4.1(ENC_A)
NetD14_C: D14.C D15.C ENC5.1(ENC_A)
NetD16_C: D16.C D17.C ENC5.4(ENC_BUTTON)

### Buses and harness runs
bus ENCA[2..0] = port ENCA[2..0]
bus ENCBUT[3..0] = port ENCBUT[3..0]

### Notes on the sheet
- Распределение битов -->
- Состояние битов -->
- 1100011000010011  -  ENC1D - MENU = 50707
- 1100011000010010  -  ENC1U - MENU = 50706
- B3-B2-000-B1-B0-A0-000-A1-00-A2-B = 50963
- 1100011100000011  -  ENC2D  - CH A  = 50947
- 1100010100010011  -  ENC1B - MENU = 50451
- 1100011100000010  -  ENC2U  - CH A  = 50946
- 1100011100010001  -  ENC3D  - CH B  = 50961
- 1100001100010011  -  ENC2B  - CH A  = 49939
- 1100011100010000  -  ENC3U  - CH B  = 50960
- 1000011100010011  -  ENC3B  - CH B  = 34579
- 1100011000000011  -  ENC4D - T/DIV = 50691
- 0100011100010011  -  ENC4B - T/DIV = 18185
- 1100011000000010  -  ENC4U - T/DIV = 50690
- 1100011000010001 - ENC5D - CURSOR = 50705
- 1100011000010000 - ENC5U - CURSOR = 50704
- 1000001100010011 - ENC5B - CURSOR = 33555

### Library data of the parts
C110-C117 = CL10C102JB8NNNC: PartName: CL10; Part Label: C0603 1nF 5% NP0 50V; Manufacturer: Samsung Electro-Mechanics; Voltage: 50V; Tolerance: 5 %; Device: C; ShortName: C0603
D5-D17 = PMEG2020EJ,115: 20V, 2A very low VF MEGA Schottky barrier rectifiers; Manufacturer: NXP Semiconductors; ClassName_u: Schottky SMD; Device: D
ENC1-ENC5 = Encoder: Rotary Encoder with button
R150 R151 = 0603SAF1002T50: as R107 on sheet Analog

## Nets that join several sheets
+2.7V: Analog (Q3.2 Q4.2 Q6.2 Q7.2), CPU (24 pins), Power (7 pins), Digital (38 pins), Encoders (R150.2 R151.2)
+3.3VA: Analog (11 pins), Power (B17.2 C91.A)
-3.3VA: Analog (12 pins), Power (B18.2 C93.C)
AGND: Analog (58 pins), Power (C91.C C93.A), Digital (12 pins)
DGND: CPU (33 pins), Power (26 pins), Digital (39 pins), Encoders (22 pins)
VUSB: CPU (5 pins), Power (C80.2 D1.2 U17.1)
ENC_B: CPU (U1.76), Encoders (5 pins)
ENC_IRQ: CPU (U1.64), Encoders (5 pins)
ENCA0: CPU (U1.73), Encoders (5 pins)
ENCA1: CPU (U1.74), Encoders (C112.2 D8.C D13.A ENC2.1)
ENCA2: CPU (U1.75), Encoders (C114.2 D10.C D15.A ENC3.1)
ENCBUT0: CPU (U1.72), Encoders (C111.2 D5.C ENC1.4)
ENCBUT1: CPU (U1.71), Encoders (C113.1 D7.C D16.A ENC2.4)
ENCBUT2: CPU (U1.70), Encoders (C115.1 D9.C D17.A ENC3.5)
ENCBUT3: CPU (U1.69), Encoders (C116.1 D11.C ENC4.4)
NetC84_2: CPU (U1.7), Power (C84.2 R132.1 R133.2)
NetR105_2: Analog (R105.2), Digital (U5.114)
NetR125_2: Analog (R125.2), Digital (U5.1)
NetU4_3: Analog (U16.3), Digital (U4.3)
NetU4_10: Analog (U16.13), Digital (U4.10)
ON_A: CPU (U1.68), Power (R137.2 R138.1 U18.1)
ON_B: CPU (U1.65), Power (R135.1 R136.1)
PWMA: CPU (U1.60), Digital (U5.96)
PWMB: CPU (U1.59), Digital (U5.97)
Q0: CPU (U1.58), Digital (U5.98)
Q1: CPU (U1.55), Digital (U5.101)
Q2: CPU (U1.54), Digital (U5.102)
Q3: CPU (U1.53), Digital (U5.103)
Q4: CPU (U1.52), Digital (U5.104)
Q5: CPU (U1.51), Digital (U5.105)
Q6: CPU (U1.50), Digital (U5.106)
Q7: CPU (U1.49), Digital (U5.107)
RD: CPU (U1.48), Digital (U5.108)
RS: CPU (U1.46), Digital (U5.109)
S1: Analog (U23.7), Digital (U4.8)
S2: Analog (U23.6), Digital (U4.9)
SPI_CS: CPU (U1.62), Digital (U5.88)
SPI_MOSI: CPU (U1.61), Digital (U5.94)
SPI_SCK: CPU (U1.63), Digital (U5.87)
SPICS: Analog (U22.12 U23.12), Digital (U5.4)
SPIMOSI: Analog (U22.14), Digital (U5.3)
SPISCK: Analog (U22.11 U23.11), Digital (U5.5)
WR: CPU (U1.47), Digital (U5.110)
WR_SRAM_RDY: CPU (U1.45), Digital (U5.111)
